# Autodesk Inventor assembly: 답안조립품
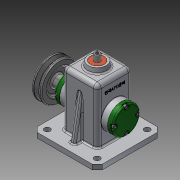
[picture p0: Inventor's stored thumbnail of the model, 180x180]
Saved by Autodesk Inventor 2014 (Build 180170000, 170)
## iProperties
Created: 2016-02
Part Number: 답안조립품
Document SubType Name: Assembly
Designer: 전형준
Author: 전형준
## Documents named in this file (16)
- C:\Users\Administrator\Desktop\460211V1033\답안조립품.iam
- C:\Users\Administrator\Desktop\460211V1033\1-본체.ipt
- C:\Users\Administrator\Desktop\460211V1033\V벨트풀리.ipt
- C:\Users\Administrator\Desktop\460211V1033\고정핀 1.2 x 10.ipt
- C:\Users\Administrator\Desktop\460211V1033\뒤커버.ipt
- C:\Users\Administrator\Desktop\460211V1033\링크.ipt
- C:\Users\Administrator\Desktop\460211V1033\멈춤나사 M3x8.ipt
- C:\Users\Administrator\Desktop\460211V1033\베어링 12 x 32 x 10.ipt
- C:\Users\Administrator\Desktop\460211V1033\볼트 M4 x 12.ipt
- C:\Users\Administrator\Desktop\460211V1033\부시.ipt
- C:\Users\Administrator\Desktop\460211V1033\슬라이드.ipt
- C:\Users\Administrator\Desktop\460211V1033\앞커버.ipt
- C:\Users\Administrator\Desktop\460211V1033\오일실 12 25 7.ipt
- C:\Users\Administrator\Desktop\460211V1033\키 4 x 4 x 10.ipt
- C:\Users\Administrator\Desktop\460211V1033\편심축.ipt
- C:\Users\Administrator\Desktop\460211V1033\핀 5 x 18.ipt
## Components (12 placed, 5 different names)
1. 1-본체:1 — 각도:1, 각도:2
2. V벨트풀리:1
3. 고정핀 1.2 x 10:1
4. 핀 5 x 18:2
5. ISO 4762 M4 x 12:2 — 각도:1
6. ISO 4762 M4 x 12:3
7. ISO 4762 M4 x 12:4
8. ISO 4762 M4 x 12:5
9. ISO 4762 M4 x 12:1 — 각도:2
10. ISO 4762 M4 x 12:6
11. ISO 4762 M4 x 12:7
12. ISO 4762 M4 x 12:8
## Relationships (2: Angle 2)
- 각도:1 [Angle]: 1-본체:1 ↔ ISO 4762 M4 x 12:2
- 각도:2 [Angle]: 1-본체:1 ↔ ISO 4762 M4 x 12:1
